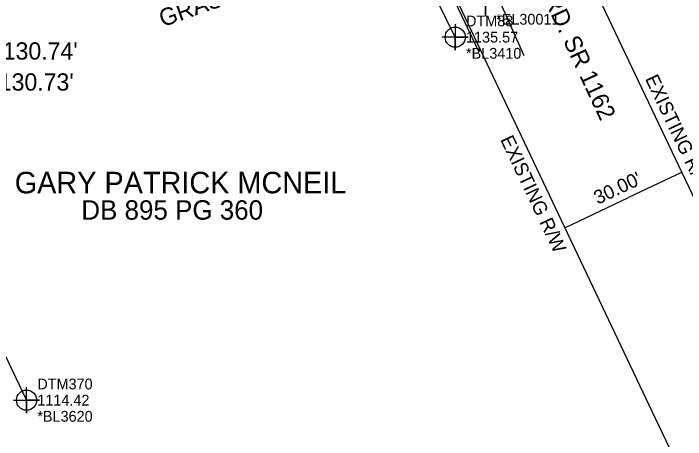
# Model space of a CAD drawing. Extents: x 1286007 to 1287145, y 857718 to 858514.
# Drawn here: x 1286682.8 to 1286838.7, y 858055.9 to 858154.7 of the extents above; entities that cross this region are included whole.
import ezdxf

# ---------------------------------------------------------------- set-up
doc = ezdxf.new("R2010")
doc.units = 0
for name, color, linetype in [('Exist Hydro Jurisdictional Stream or Body of Water', 7, 'Continuous'), ('Exist Hydro Stream or Body of Water Cogo Comment', 7, 'Continuous'), ('Exist Hydro Stream or Body of Water Cogo Elevation', 7, 'Continuous'), ('Exist Hydro Stream or Body of Water Cogo Number', 7, 'Continuous'), ('Exist Hydro Stream or Body of Water Cogo Point CELL', 7, 'Continuous'), ('Exist Other Culture Fence Line', 7, 'Continuous'), ('Exist Other Culture Fence Line Cogo Comment', 7, 'Continuous'), ('Exist Other Culture Fence Line Cogo Elevation', 7, 'Continuous'), ('Exist Other Culture Fence Line Cogo Number', 7, 'Continuous'), ('Exist Other Culture Fence Line Cogo Point CELL', 7, 'Continuous'), ('Exist Property Deed Book Text', 7, 'Continuous'), ('Exist Property Owner Text', 7, 'Continuous'), ('Exist Right of Way Line', 7, 'Continuous'), ('Exist Right of Way Line Text', 7, 'Continuous'), ('Exist Right of Way Width CELL', 7, 'Continuous'), ('Exist Roads EOP Cogo Comment', 7, 'Continuous'), ('Exist Roads EOP Cogo Point CELL', 7, 'Continuous'), ('Exist Roads EOP Leader', 7, 'Continuous'), ('Exist Roads EOP Text', 7, 'Continuous'), ('Exist Structure Major Bridge Seat Top Elevation', 7, 'Continuous'), ('Exist Utilities Telephone UG Cable', 7, 'Continuous'), ('Exist Vegetation Tree Text', 7, 'Continuous')]:
    doc.layers.add(name, color=color, linetype=linetype)

msp = doc.modelspace()

# ---------------------------------------------------------------- linework, layer by layer
at = {"layer": 'Exist Hydro Jurisdictional Stream or Body of Water'}
msp.add_lwpolyline([(1286637.89, 858162.5), (1286641.01, 858153.51), (1286665.78, 858106.89), (1286685.86, 858065.01)], dxfattribs=at)
at = {"layer": 'Exist Hydro Stream or Body of Water Cogo Point CELL'}
msp.add_lwpolyline([(1286682.86, 858065.01), (1286688.86, 858065.01), (1286685.86, 858065.01), (1286685.86, 858062.01), (1286685.86, 858068.01)], dxfattribs=at)
msp.add_circle((1286685.86, 858065.01), 2.34, dxfattribs=at)
at = {"layer": 'Exist Other Culture Fence Line'}
msp.add_line((1286785.28, 858149.22), (1286764.23, 858192.2), dxfattribs=at)
at = {"layer": 'Exist Other Culture Fence Line Cogo Point CELL'}
msp.add_lwpolyline([(1286785.28, 858152.22), (1286785.28, 858146.22), (1286785.28, 858149.22), (1286788.28, 858149.22), (1286782.28, 858149.22)], dxfattribs=at)
msp.add_circle((1286785.28, 858149.22), 2.34, dxfattribs=at)
at = {"layer": 'Exist Right of Way Line'}
for p, q in [((1286749.61, 858303.72), (1286858.72, 858073.71)), ((1286766.45, 858198.24), (1286831.62, 858060.85)), ((1286831.62, 858060.85), (1286880.71, 857959.15))]:
    msp.add_line(p, q, dxfattribs=at)
msp.add_arc((1287151.68, 857086.65), 1175, 111.95838, 115.04397, dxfattribs=at)
at = {"layer": 'Exist Right of Way Width CELL'}
for p in [(1286837.78, 858117.86), (1286810.68, 858105)]:
    msp.add_line(p, (1286825.48, 858112.02), dxfattribs=at)
at = {"layer": 'Exist Roads EOP Cogo Point CELL'}
msp.add_lwpolyline([(1286792.26, 858160.12), (1286792.26, 858154.12), (1286792.26, 858157.12), (1286795.26, 858157.12), (1286789.26, 858157.12)], dxfattribs=at)
at = {"layer": 'Exist Roads EOP Leader'}
msp.add_line((1286801.24, 858144.9), (1286795.03, 858158.84), dxfattribs=at)
at = {"layer": 'Exist Utilities Telephone UG Cable'}
msp.add_lwpolyline([(1286725.04, 858292.45), (1286739.69, 858262.93), (1286740.75, 858253.32), (1286734.85, 858234.65), (1286728.02, 858227.21), (1286741.27, 858196.85), (1286752.3, 858197.7), (1286768.6, 858192.43), (1286790.74, 858145.79)], dxfattribs=at)

# ---------------------------------------------------------------- texts
at = {"layer": 'Exist Hydro Stream or Body of Water Cogo Comment'}
msp.add_text('*BL3620', height=2.5, dxfattribs=at).set_placement((1286688.36, 858060.01))
at = {"layer": 'Exist Hydro Stream or Body of Water Cogo Elevation'}
msp.add_text('1114.42', height=2.5, dxfattribs=at).set_placement((1286688.36, 858063.76))
at = {"layer": 'Exist Hydro Stream or Body of Water Cogo Number'}
msp.add_text('DTM370', height=2.5, dxfattribs=at).set_placement((1286688.36, 858067.51))
at = {"layer": 'Exist Other Culture Fence Line Cogo Comment'}
msp.add_text('*BL3410', height=2.5, dxfattribs=at).set_placement((1286787.78, 858144.22))
at = {"layer": 'Exist Other Culture Fence Line Cogo Elevation'}
msp.add_text('1135.57', height=2.5, dxfattribs=at).set_placement((1286787.78, 858147.97))
at = {"layer": 'Exist Other Culture Fence Line Cogo Number'}
msp.add_text('DTM88', height=2.5, dxfattribs=at).set_placement((1286787.78, 858151.72))
at = {"layer": 'Exist Property Deed Book Text'}
msp.add_text('DB 895 PG 360', height=4.5, rotation=360, dxfattribs=at).set_placement((1286698.56, 858106.88))
at = {"layer": 'Exist Property Owner Text'}
msp.add_text('GARY PATRICK MCNEIL', height=5, dxfattribs=at).set_placement((1286683.12, 858112.98))
at = {"layer": 'Exist Right of Way Line Text'}
for p in [(1286829.24, 858139.59), (1286795.65, 858125.48)]:
    msp.add_text('EXISTING R/W', height=3.2, rotation=295.3785, dxfattribs=at).set_placement(p)
at = {"layer": 'Exist Right of Way Width CELL'}
msp.add_text("30.00'", height=3.2, rotation=25.3785, dxfattribs=at).set_placement((1286818.36, 858110.33))
at = {"layer": 'Exist Roads EOP Cogo Comment'}
msp.add_text('*EL30011', height=2.5, dxfattribs=at).set_placement((1286794.76, 858152.12))
at = {"layer": 'Exist Roads EOP Text'}
msp.add_text('ELK CREEK DARBY RD. SR 1162', height=4, rotation=295.0055, dxfattribs=at).set_placement((1286783.96, 858204.72))
at = {"layer": 'Exist Structure Major Bridge Seat Top Elevation'}
for s, p in [("SEAT=1130.74'", (1286660.27, 858144.02)), ("SEAT=1130.73'", (1286659.35, 858136.82))]:
    msp.add_text(s, height=4, dxfattribs=at).set_placement(p)
at = {"layer": 'Exist Vegetation Tree Text'}
msp.add_text('GRASS', height=4, rotation=19.4285, dxfattribs=at).set_placement((1286717.44, 858151.52))

doc.saveas('drawing.dxf')
